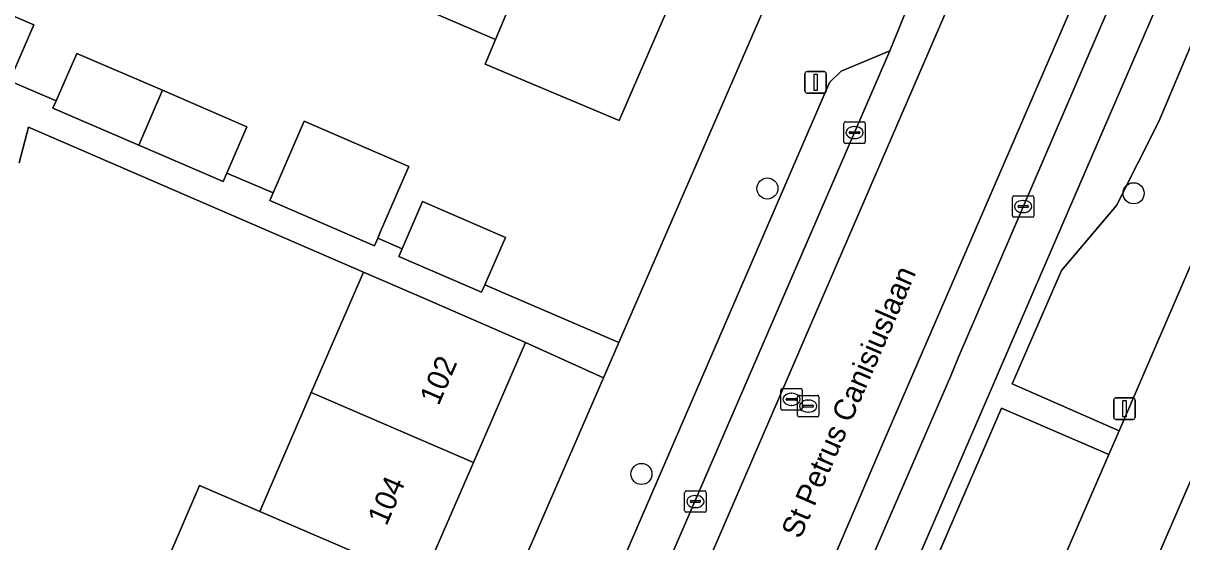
# Model space of a CAD drawing. Extents: x 162803 to 163818, y 381639 to 382475.
# Drawn here: x 163372.1 to 163425.9, y 381903.2 to 381927.2 of the extents above; entities that cross this region are included whole.
import ezdxf

# ---------------------------------------------------------------- set-up
doc = ezdxf.new("R2010")
doc.units = 0
for name, color, linetype in [('IMGEO_Berm_groen', 7, 'Continuous'), ('IMGEO_Boom', 7, 'Continuous'), ('IMGEO_Erf', 7, 'Continuous'), ('IMGEO_Kolk', 7, 'Continuous'), ('IMGEO_Lichtmast', 7, 'Continuous'), ('IMGEO_Openbare_ruimte_label', 7, 'Continuous'), ('IMGEO_Pand', 7, 'Continuous'), ('IMGEO_Pand_nummerreeks', 7, 'Continuous'), ('IMGEO_Parkeervlak_open', 7, 'Continuous'), ('IMGEO_Rijbaan_lokaal_gesloten', 7, 'Continuous'), ('IMGEO_Rioolput', 7, 'Continuous'), ('IMGEO_Voetpad_open', 7, 'Continuous')]:
    doc.layers.add(name, color=color, linetype=linetype)

msp = doc.modelspace()

# ---------------------------------------------------------------- linework, layer by layer
at = {"layer": 'IMGEO_Berm_groen'}
for points in [[(163430.297, 381925.219), (163426.581, 381926.812), (163424.833, 381922.667), (163422.867, 381918.772), (163420.305, 381915.765), (163418.016, 381910.493), (163422.983, 381908.314)], [(163422.504, 381907.226), (163417.526, 381909.368), (163411.623, 381895.743), (163411.542, 381895.555), (163416.497, 381893.39)]]:
    msp.add_lwpolyline(points, close=True, dxfattribs=at)
at = {"layer": 'IMGEO_Boom'}
for centre in [(163406.65, 381919.561), (163423.656, 381919.338), (163400.801, 381906.318)]:
    msp.add_circle(centre, 0.489, dxfattribs=at)
at = {"layer": 'IMGEO_Erf'}
for points in [[(163394.019, 381926.474), (163393.907, 381926.523), (163389.411, 381928.473), (163387.886, 381929.134), (163388.608, 381930.798), (163382.581, 381933.411), (163376.439, 381936.074), (163370.425, 381938.682), (163373.829, 381946.533), (163370.045, 381948.172), (163370.933, 381950.319), (163356.875, 381956.335)], [(163408.469, 381934.011), (163401.592, 381936.98), (163399.84, 381932.939), (163403.51, 381931.348), (163400.943, 381925.429), (163399.77, 381922.723), (163393.54, 381925.328), (163394.019, 381926.474)], [(163371.457, 381924.553), (163373.622, 381923.634), (163374.586, 381925.831), (163378.552, 381924.121), (163382.477, 381922.429), (163381.547, 381920.271), (163383.692, 381919.361), (163385.131, 381922.681), (163389.991, 381920.575), (163389.505, 381919.452), (163388.686, 381917.56), (163388.554, 381917.254), (163389.683, 381916.765), (163390.634, 381918.963), (163394.484, 381917.295), (163393.532, 381915.097), (163399.744, 381912.413), (163408.803, 381933.235)], [(163368.596, 381928.872), (163372.581, 381927.153), (163371.589, 381924.859)], [(163433.958, 381923.664), (163403.547, 381853.528)], [(163360.756, 381889.214), (163382.615, 381873.04), (163399.032, 381910.776), (163395.415, 381912.423), (163392.995, 381906.846), (163390.606, 381901.339), (163388.216, 381895.832), (163385.827, 381890.325), (163383.437, 381884.818), (163380.883, 381878.932), (163376.297, 381880.923), (163373.361, 381882.197), (163369.875, 381883.71), (163372.439, 381889.62), (163372.282, 381889.688), (163374.66, 381895.206), (163377.011, 381900.661), (163377.908, 381900.274), (163380.284, 381905.787), (163383.075, 381904.584), (163385.465, 381910.091), (163387.89, 381915.681), (163372.342, 381922.402), (163371.895, 381920.756)]]:
    msp.add_lwpolyline(points, dxfattribs=at)
at = {"layer": 'IMGEO_Kolk'}
for p, q in [((163410.195, 381921.728), (163410.195, 381922.58)), ((163410.27, 381922.654), (163411.122, 381922.654)), ((163411.196, 381922.58), (163411.196, 381921.728)), ((163410.454, 381922.148), (163410.454, 381922.16)), ((163410.892, 381922.111), (163410.494, 381922.111)), ((163410.497, 381922.197), (163410.895, 381922.197)), ((163410.683, 381922.434), (163410.708, 381922.434)), ((163410.938, 381922.16), (163410.938, 381922.148)), ((163411.122, 381921.654), (163410.27, 381921.654)), ((163410.706, 381921.874), (163410.681, 381921.874)), ((163418.025, 381918.299), (163418.025, 381919.151)), ((163418.1, 381919.225), (163418.952, 381919.225)), ((163418.327, 381918.768), (163418.725, 381918.768)), ((163418.513, 381919.005), (163418.538, 381919.005)), ((163419.026, 381919.151), (163419.026, 381918.299)), ((163418.952, 381918.225), (163418.1, 381918.225)), ((163418.284, 381918.719), (163418.284, 381918.731)), ((163418.722, 381918.682), (163418.324, 381918.682)), ((163418.536, 381918.445), (163418.511, 381918.445)), ((163418.768, 381918.731), (163418.768, 381918.719)), ((163402.807, 381904.614), (163402.807, 381905.466)), ((163402.882, 381905.54), (163403.734, 381905.54)), ((163403.295, 381905.32), (163403.32, 381905.32)), ((163403.808, 381905.466), (163403.808, 381904.614)), ((163403.066, 381905.034), (163403.066, 381905.046)), ((163403.504, 381904.997), (163403.106, 381904.997)), ((163403.109, 381905.083), (163403.507, 381905.083)), ((163403.55, 381905.046), (163403.55, 381905.034)), ((163403.734, 381904.54), (163402.882, 381904.54)), ((163403.318, 381904.76), (163403.293, 381904.76))]:
    msp.add_line(p, q, dxfattribs=at)
for points in [[(163410.195, 381921.728), (163410.195, 381922.58)], [(163410.27, 381922.654), (163411.122, 381922.654)], [(163411.196, 381922.58), (163411.196, 381921.728)], [(163411.122, 381921.654), (163410.27, 381921.654)], [(163418.025, 381918.299), (163418.025, 381919.151)], [(163418.1, 381919.225), (163418.952, 381919.225)], [(163419.026, 381919.151), (163419.026, 381918.299)], [(163418.952, 381918.225), (163418.1, 381918.225)], [(163402.807, 381904.614), (163402.807, 381905.466)], [(163402.882, 381905.54), (163403.734, 381905.54)], [(163403.808, 381905.466), (163403.808, 381904.614)], [(163403.734, 381904.54), (163402.882, 381904.54)]]:
    msp.add_lwpolyline(points, dxfattribs=at)
for centre, radius, start, end in [((163410.272, 381922.578), 0.0765, 91.552, 178.448), ((163410.272, 381922.578), 0.0765, 91.552, 178.448), ((163411.12, 381922.578), 0.0765, 1.552, 88.448), ((163411.12, 381922.578), 0.0765, 1.552, 88.448), ((163410.494, 381922.157), 0.0403, 85.8775, 175.7526), ((163410.491, 381922.147), 0.0366, 178.938, 274.7102), ((163410.895, 381922.154), 0.043, 264.8664, 352.4533), ((163410.899, 381922.159), 0.0386, 1.7309, 96.639), ((163410.272, 381921.73), 0.0765, 181.552, 268.448), ((163410.272, 381921.73), 0.0765, 181.552, 268.448), ((163411.12, 381921.73), 0.0765, 271.552, 358.448), ((163411.12, 381921.73), 0.0765, 271.552, 358.448), ((163418.102, 381919.149), 0.0765, 91.552, 178.448), ((163418.102, 381919.149), 0.0765, 91.552, 178.448), ((163418.324, 381918.728), 0.0403, 85.8775, 175.7526), ((163418.729, 381918.73), 0.0386, 1.7309, 96.639), ((163418.95, 381919.149), 0.0765, 1.552, 88.448), ((163418.95, 381919.149), 0.0765, 1.552, 88.448), ((163418.102, 381918.301), 0.0765, 181.552, 268.448), ((163418.102, 381918.301), 0.0765, 181.552, 268.448), ((163418.321, 381918.718), 0.0366, 178.938, 274.7102), ((163418.725, 381918.725), 0.043, 264.8664, 352.4533), ((163418.95, 381918.301), 0.0765, 271.552, 358.448), ((163418.95, 381918.301), 0.0765, 271.552, 358.448), ((163402.884, 381905.464), 0.0765, 91.552, 178.448), ((163402.884, 381905.464), 0.0765, 91.552, 178.448), ((163403.732, 381905.464), 0.0765, 1.552, 88.448), ((163403.732, 381905.464), 0.0765, 1.552, 88.448), ((163403.106, 381905.043), 0.0403, 85.8775, 175.7526), ((163403.103, 381905.033), 0.0366, 178.938, 274.7102), ((163403.507, 381905.04), 0.043, 264.8664, 352.4533), ((163403.511, 381905.045), 0.0386, 1.7309, 96.639), ((163402.884, 381904.616), 0.0765, 181.552, 268.448), ((163402.884, 381904.616), 0.0765, 181.552, 268.448), ((163403.732, 381904.616), 0.0765, 271.552, 358.448), ((163403.732, 381904.616), 0.0765, 271.552, 358.448)]:
    msp.add_arc(centre, radius, start, end, dxfattribs=at)
for centre, major_axis, ratio, start_param, end_param in [((163410.682, 381922.154), (-0.387, 0.002), 0.722429, 4.712389, 7.853982), ((163410.707, 381922.154), (-0.39, 0.002), 0.717154, 1.570796, 4.712389), ((163418.512, 381918.725), (-0.387, 0.002), 0.722429, 4.712389, 7.853982), ((163418.537, 381918.725), (-0.39, 0.002), 0.717154, 1.570796, 4.712389), ((163403.294, 381905.04), (-0.387, 0.002), 0.722429, 4.712389, 7.853982), ((163403.319, 381905.04), (-0.39, 0.002), 0.717154, 1.570796, 4.712389)]:
    msp.add_ellipse(centre, major_axis=major_axis, ratio=ratio, start_param=start_param, end_param=end_param, dxfattribs=at)
at = {"layer": 'IMGEO_Lichtmast'}
for p, q in [((163408.394, 381924.084), (163408.394, 381924.884)), ((163408.394, 381924.884), (163408.394, 381924.084)), ((163408.494, 381924.984), (163409.284, 381924.984)), ((163409.284, 381924.984), (163408.494, 381924.984)), ((163409.384, 381924.884), (163409.384, 381924.084)), ((163409.384, 381924.084), (163409.384, 381924.884)), ((163409.284, 381923.984), (163408.494, 381923.984)), ((163408.494, 381923.984), (163409.284, 381923.984)), ((163422.735, 381908.951), (163422.735, 381909.751)), ((163422.735, 381909.751), (163422.735, 381908.951)), ((163422.835, 381909.851), (163423.625, 381909.851)), ((163423.625, 381909.851), (163422.835, 381909.851)), ((163423.725, 381909.751), (163423.725, 381908.951)), ((163423.725, 381908.951), (163423.725, 381909.751)), ((163423.625, 381908.851), (163422.835, 381908.851)), ((163422.835, 381908.851), (163423.625, 381908.851))]:
    msp.add_line(p, q, dxfattribs=at)
for points in [[(163408.814, 381924.859), (163408.964, 381924.859), (163408.964, 381924.109), (163408.814, 381924.109), (163408.814, 381924.859)], [(163423.155, 381909.726), (163423.305, 381909.726), (163423.305, 381908.976), (163423.155, 381908.976), (163423.155, 381909.726)]]:
    msp.add_lwpolyline(points, dxfattribs=at)
for centre, start, end in [((163408.494, 381924.884), 90, 180), ((163408.494, 381924.884), 90, 180), ((163409.284, 381924.884), 0, 90), ((163409.284, 381924.884), 360, 90), ((163408.494, 381924.084), 180, 270), ((163408.494, 381924.084), 180, 270), ((163409.284, 381924.084), 270, 0), ((163409.284, 381924.084), 270, 0), ((163422.835, 381909.751), 90, 180), ((163422.835, 381909.751), 90, 180), ((163423.625, 381909.751), 0, 90), ((163423.625, 381909.751), 360, 90), ((163422.835, 381908.951), 180, 270), ((163422.835, 381908.951), 180, 270), ((163423.625, 381908.951), 270, 0), ((163423.625, 381908.951), 270, 0)]:
    msp.add_arc(centre, 0.1, start, end, dxfattribs=at)
at = {"layer": 'IMGEO_Pand'}
for points in [[(163397.801, 381935.519), (163395.324, 381936.593), (163394.696, 381935.145), (163393.792, 381935.537), (163395.546, 381939.582), (163392.933, 381940.714), (163391.177, 381936.664), (163388.608, 381930.798), (163387.886, 381929.134), (163389.411, 381928.473), (163393.907, 381926.523), (163394.019, 381926.474), (163394.712, 381928.131)], [(163399.84, 381932.939), (163401.592, 381936.98), (163398.934, 381938.133), (163397.801, 381935.519), (163394.712, 381928.131), (163394.019, 381926.474), (163393.54, 381925.328), (163399.77, 381922.723), (163400.943, 381925.429), (163403.51, 381931.348)], [(163372.581, 381927.153), (163368.596, 381928.872), (163367.606, 381926.577), (163367.464, 381926.247), (163367.372, 381926.034), (163371.353, 381924.312), (163371.457, 381924.553), (163371.589, 381924.859)], [(163373.622, 381923.634), (163373.473, 381923.294), (163377.455, 381921.577), (163378.552, 381924.121), (163374.586, 381925.831)], [(163378.552, 381924.121), (163377.455, 381921.577), (163381.38, 381919.884), (163381.547, 381920.271), (163382.477, 381922.429)], [(163389.991, 381920.575), (163385.131, 381922.681), (163383.692, 381919.361), (163383.539, 381919.009), (163388.401, 381916.902), (163388.554, 381917.254), (163388.686, 381917.56), (163389.505, 381919.452)], [(163394.484, 381917.295), (163390.634, 381918.963), (163389.683, 381916.765), (163389.53, 381916.413), (163393.379, 381914.745), (163393.532, 381915.097)], [(163392.995, 381906.846), (163395.415, 381912.423), (163390.827, 381914.409), (163387.89, 381915.681), (163385.465, 381910.091)], [(163383.075, 381904.584), (163390.606, 381901.339), (163392.995, 381906.846), (163385.465, 381910.091)], [(163390.606, 381901.339), (163383.075, 381904.584), (163380.284, 381905.787), (163377.908, 381900.274), (163380.686, 381899.077), (163388.216, 381895.832)]]:
    msp.add_lwpolyline(points, close=True, dxfattribs=at)
at = {"layer": 'IMGEO_Parkeervlak_open'}
msp.add_lwpolyline([(163428.637, 381938.178), (163428.395, 381941.649), (163415.513, 381911.701), (163415.161, 381910.87), (163390.76, 381854.593), (163388.624, 381850.595), (163390.992, 381851.096), (163391.608, 381851.487), (163393.741, 381856.431), (163394.843, 381858.942), (163409.434, 381892.715), (163410.903, 381896.072), (163428.446, 381936.631)], dxfattribs=at)
msp.add_lwpolyline([(163383.331, 381858.993), (163412.342, 381925.941), (163410.077, 381924.998), (163409.535, 381924.479), (163382.506, 381862.028), (163382.482, 381861.246)], close=True, dxfattribs=at)
at = {"layer": 'IMGEO_Rijbaan_lokaal_gesloten'}
for points in [[(163464.855, 382026.022), (163465.999, 382028.125), (163464.722, 382028.665), (163461.877, 382023.605), (163459.619, 382019.017), (163457.08, 382012.454), (163453.694, 382003.844), (163449.038, 381993.259), (163431.05, 381951.693), (163412.004, 381907.726), (163394.228, 381866.23), (163390.489, 381857.832), (163387.456, 381851.551), (163383.033, 381843.676), (163380.997, 381839.984), (163379.217, 381836.772), (163388.531, 381831.246)], [(163386.919, 381847.797), (163388.624, 381850.595), (163390.76, 381854.593), (163415.161, 381910.87), (163415.513, 381911.701), (163428.395, 381941.649), (163430.131, 381945.733), (163435.996, 381959.252), (163447.726, 381986.331), (163453.528, 381999.71), (163453.677, 382000.069), (163454.983, 382003.129), (163456.608, 382007.035), (163457.866, 382010.228), (163459.612, 382015.187)], [(163423.149, 381946.753), (163403.398, 381901.092), (163388.514, 381866.371), (163385.128, 381859.173), (163382.589, 381854.092), (163378.39, 381846.715), (163376.357, 381843.146), (163372.645, 381836.644), (163370.396, 381832.624), (163367.968, 381828.451), (163367.924, 381828.37), (163370.398, 381827.031), (163376.97, 381838.106), (163379.217, 381836.772), (163380.997, 381839.984), (163383.033, 381843.676), (163387.456, 381851.551), (163390.489, 381857.832), (163394.228, 381866.23), (163412.004, 381907.726), (163431.05, 381951.693)], [(163413.671, 381929.232), (163412.342, 381925.941), (163383.331, 381858.993), (163380.705, 381854.126), (163379.34, 381851.695), (163379.176, 381851.082), (163375.018, 381844.043), (163371.379, 381837.387), (163367.345, 381830.172), (163366.609, 381829.082), (163367.924, 381828.37), (163367.968, 381828.451), (163370.396, 381832.624), (163372.645, 381836.644), (163376.357, 381843.146), (163378.39, 381846.715), (163382.589, 381854.092), (163385.128, 381859.173), (163388.514, 381866.371), (163403.398, 381901.092), (163423.149, 381946.753)]]:
    msp.add_lwpolyline(points, dxfattribs=at)
at = {"layer": 'IMGEO_Rioolput'}
for p, q in [((163407.269, 381909.354), (163407.269, 381910.206)), ((163407.344, 381910.28), (163408.196, 381910.28)), ((163408.27, 381910.206), (163408.27, 381909.354)), ((163407.528, 381909.774), (163407.528, 381909.786)), ((163407.966, 381909.737), (163407.568, 381909.737)), ((163407.571, 381909.823), (163407.969, 381909.823)), ((163407.757, 381910.06), (163407.782, 381910.06)), ((163408.012, 381909.786), (163408.012, 381909.774)), ((163408.042, 381909.04), (163408.042, 381909.892)), ((163408.117, 381909.966), (163408.969, 381909.966)), ((163408.53, 381909.746), (163408.555, 381909.746)), ((163409.043, 381909.892), (163409.043, 381909.04)), ((163408.196, 381909.28), (163407.344, 381909.28)), ((163407.78, 381909.5), (163407.755, 381909.5)), ((163408.301, 381909.46), (163408.301, 381909.472)), ((163408.739, 381909.423), (163408.341, 381909.423)), ((163408.344, 381909.509), (163408.742, 381909.509)), ((163408.553, 381909.186), (163408.528, 381909.186)), ((163408.785, 381909.472), (163408.785, 381909.46)), ((163408.969, 381908.966), (163408.117, 381908.966))]:
    msp.add_line(p, q, dxfattribs=at)
for points in [[(163407.269, 381909.354), (163407.269, 381910.206)], [(163407.344, 381910.28), (163408.196, 381910.28)], [(163408.27, 381910.206), (163408.27, 381909.354)], [(163408.042, 381909.04), (163408.042, 381909.892)], [(163408.117, 381909.966), (163408.969, 381909.966)], [(163409.043, 381909.892), (163409.043, 381909.04)], [(163408.196, 381909.28), (163407.344, 381909.28)], [(163408.969, 381908.966), (163408.117, 381908.966)]]:
    msp.add_lwpolyline(points, dxfattribs=at)
for centre, radius, start, end in [((163407.346, 381910.204), 0.0765, 91.552, 178.448), ((163407.346, 381910.204), 0.0765, 91.552, 178.448), ((163408.194, 381910.204), 0.0765, 1.552, 88.448), ((163408.194, 381910.204), 0.0765, 1.552, 88.448), ((163407.568, 381909.783), 0.0403, 85.8775, 175.7526), ((163407.565, 381909.773), 0.0366, 178.938, 274.7102), ((163407.969, 381909.78), 0.043, 264.8664, 352.4533), ((163407.973, 381909.785), 0.0386, 1.7309, 96.639), ((163408.119, 381909.89), 0.0765, 91.552, 178.448), ((163408.119, 381909.89), 0.0765, 91.552, 178.448), ((163408.967, 381909.89), 0.0765, 1.552, 88.448), ((163408.967, 381909.89), 0.0765, 1.552, 88.448), ((163407.346, 381909.356), 0.0765, 181.552, 268.448), ((163407.346, 381909.356), 0.0765, 181.552, 268.448), ((163408.194, 381909.356), 0.0765, 271.552, 358.448), ((163408.194, 381909.356), 0.0765, 271.552, 358.448), ((163408.341, 381909.469), 0.0403, 85.8775, 175.7526), ((163408.338, 381909.459), 0.0366, 178.938, 274.7102), ((163408.742, 381909.466), 0.043, 264.8664, 352.4533), ((163408.746, 381909.471), 0.0386, 1.7309, 96.639), ((163408.119, 381909.042), 0.0765, 181.552, 268.448), ((163408.119, 381909.042), 0.0765, 181.552, 268.448), ((163408.967, 381909.042), 0.0765, 271.552, 358.448), ((163408.967, 381909.042), 0.0765, 271.552, 358.448)]:
    msp.add_arc(centre, radius, start, end, dxfattribs=at)
for centre, major_axis, ratio, start_param, end_param in [((163407.756, 381909.78), (-0.387, 0.002), 0.722429, 4.712389, 7.853982), ((163407.781, 381909.78), (-0.39, 0.002), 0.717154, 1.570796, 4.712389), ((163408.529, 381909.466), (-0.387, 0.002), 0.722429, 4.712389, 7.853982), ((163408.554, 381909.466), (-0.39, 0.002), 0.717154, 1.570796, 4.712389)]:
    msp.add_ellipse(centre, major_axis=major_axis, ratio=ratio, start_param=start_param, end_param=end_param, dxfattribs=at)
at = {"layer": 'IMGEO_Voetpad_open'}
msp.add_lwpolyline([(163433.958, 381923.664), (163434.604, 381925.154), (163442.096, 381942.431), (163438.452, 381944.062), (163430.782, 381926.338), (163430.297, 381925.219), (163422.983, 381908.314), (163422.504, 381907.226), (163416.497, 381893.39), (163415.281, 381890.601), (163414.692, 381889.232), (163409.552, 381877.287), (163409.054, 381876.142), (163400.375, 381856.069), (163399.544, 381854.142), (163392.292, 381837.534), (163395.819, 381835.705), (163403.019, 381852.311), (163403.547, 381853.528)], close=True, dxfattribs=at)
for points in [[(163428.446, 381936.631), (163410.903, 381896.072), (163409.434, 381892.715), (163394.843, 381858.942), (163393.741, 381856.431), (163391.608, 381851.487), (163390.992, 381851.096), (163388.624, 381850.595), (163386.919, 381847.797)], [(163411.274, 381935.45), (163408.803, 381933.235), (163399.744, 381912.413), (163399.032, 381910.776), (163382.615, 381873.04), (163382.117, 381871.898), (163373.793, 381852.764), (163370.544, 381852.016), (163367.354, 381849.084)], [(163383.331, 381858.993), (163382.482, 381861.246), (163382.506, 381862.028), (163409.535, 381924.479), (163410.077, 381924.998), (163412.342, 381925.941), (163413.671, 381929.232)], [(163392.212, 381850.821), (163394.49, 381856.13), (163394.559, 381856.298), (163399.544, 381854.142), (163400.375, 381856.069), (163395.432, 381858.233), (163395.584, 381858.623), (163404.123, 381878.369), (163409.054, 381876.142), (163409.552, 381877.287), (163404.619, 381879.496), (163410.04, 381892.066), (163410.179, 381892.389), (163410.346, 381892.771), (163411.542, 381895.555), (163411.623, 381895.743), (163417.526, 381909.368), (163422.504, 381907.226), (163422.983, 381908.314), (163418.016, 381910.493), (163420.305, 381915.765), (163422.867, 381918.772), (163424.833, 381922.667), (163426.581, 381926.812)], [(163371.895, 381920.756), (163372.342, 381922.402), (163387.89, 381915.681), (163390.827, 381914.409), (163395.415, 381912.423), (163399.032, 381910.776), (163399.744, 381912.413), (163393.532, 381915.097), (163393.379, 381914.745), (163389.53, 381916.413), (163389.683, 381916.765), (163388.554, 381917.254), (163388.401, 381916.902), (163383.539, 381919.009), (163383.692, 381919.361), (163381.547, 381920.271), (163381.38, 381919.884), (163377.455, 381921.577), (163373.473, 381923.294), (163373.622, 381923.634), (163371.457, 381924.553)]]:
    msp.add_lwpolyline(points, dxfattribs=at)

# ---------------------------------------------------------------- texts
at = {"layer": 'IMGEO_Openbare_ruimte_label'}
msp.add_text('St Petrus Canisiuslaan', height=1, rotation=66.4854, dxfattribs=at).set_placement((163408.174, 381903.267))
at = {"layer": 'IMGEO_Pand_nummerreeks'}
for s, p in [('102', (163391.379, 381909.452)), ('104', (163388.958, 381903.872))]:
    msp.add_text(s, height=1, rotation=66.5436, dxfattribs=at).set_placement(p)

doc.saveas('drawing.dxf')
